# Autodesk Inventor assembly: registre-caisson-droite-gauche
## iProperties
Author: chr
Created: 2001-06
Part Number: registre-caisson-droite-gauche
Document SubType Name: Assemblage
Designer: chr
Control State: 0
Master: False
Checked Out: False
PropertySet Name: Design Tracking Control
Shininess: 21.0
PropertySet Name: _Private Model Information
Length Units: 11269
Angle Units: 11286
Time Units: 11279
Mass Units: 11290
Length Display Precision: 3
Angle Display Precision: 2
Compacted: False
Density: 0.0
Volumn: 0.0
Area: 0.0
PropertySet Name: Model Information
